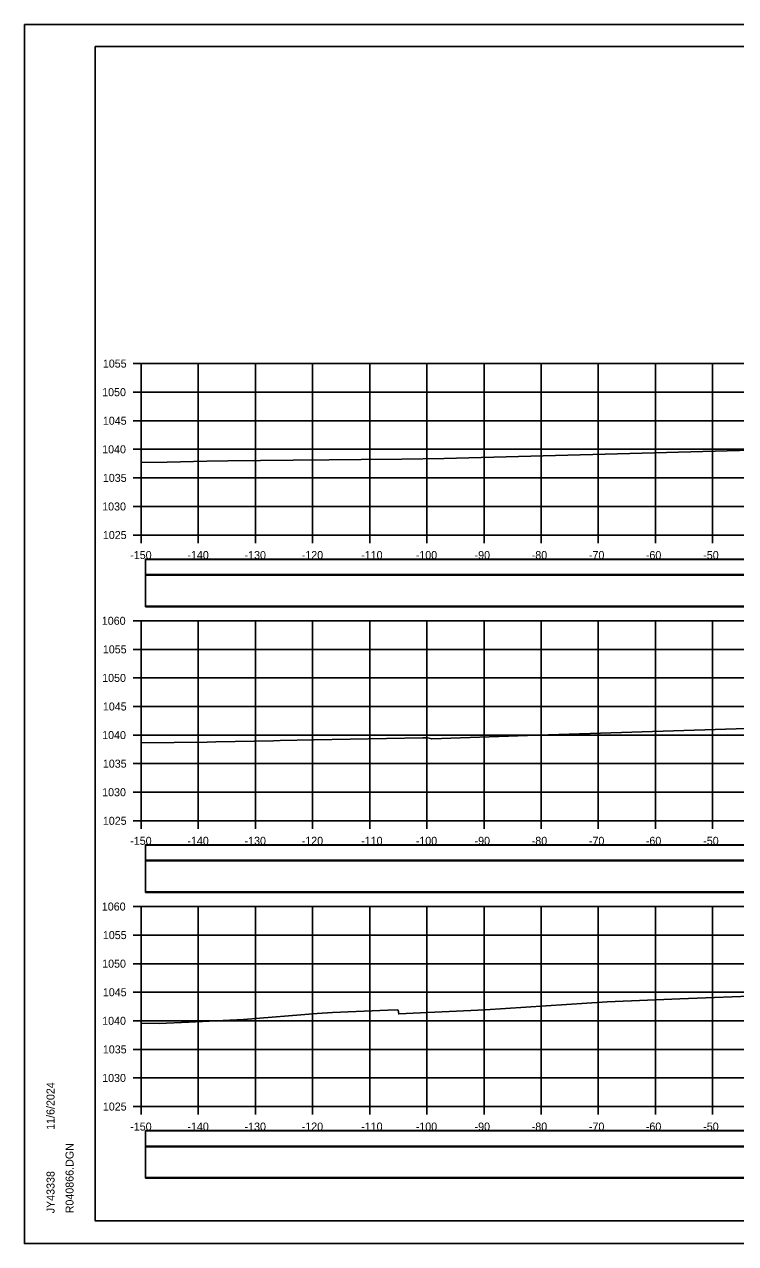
# Model space of a CAD drawing. Extents: x 1370565 to 1374448, y 301010 to 304637.
# Drawn here: x 1373198.4 to 1373322.8, y 301298.3 to 301511.7 of the extents above; entities that cross this region are included whole.
import ezdxf

# ---------------------------------------------------------------- set-up
doc = ezdxf.new("R2010")
doc.units = 0
for name, color, linetype in [('Default', 7, 'Continuous'), ('R_Axis', 7, 'Continuous'), ('R_Axis Annot', 7, 'Continuous'), ('R_Border', 7, 'Continuous'), ('R_Drive', 7, 'Continuous'), ('R_Exist Surface', 7, 'Continuous'), ('R_Grid', 7, 'Continuous'), ('R_No Plot', 7, 'Continuous')]:
    doc.layers.add(name, color=color, linetype=linetype)

msp = doc.modelspace()

# ---------------------------------------------------------------- linework, layer by layer
at = {"layer": 'Default'}
for points in [[(1373219.61, 301415.34), (1373518.02, 301415.34), (1373518.02, 301418.04), (1373219.61, 301418.04)], [(1373219.61, 301409.76), (1373518.02, 301409.76), (1373518.02, 301415.28), (1373219.61, 301415.28)], [(1373219.61, 301365.34), (1373518.02, 301365.34), (1373518.02, 301368.04), (1373219.61, 301368.04)], [(1373219.61, 301359.76), (1373518.02, 301359.76), (1373518.02, 301365.28), (1373219.61, 301365.28)], [(1373219.61, 301315.34), (1373518.02, 301315.34), (1373518.02, 301318.04), (1373219.61, 301318.04)], [(1373219.61, 301309.76), (1373518.02, 301309.76), (1373518.02, 301315.28), (1373219.61, 301315.28)]]:
    msp.add_lwpolyline(points, close=True, dxfattribs=at)
at = {"layer": 'R_Axis'}
for p, q in [((1373217.41, 301452.3), (1373218.81, 301452.3)), ((1373218.81, 301422.3), (1373218.81, 301452.3)), ((1373217.41, 301447.3), (1373218.81, 301447.3)), ((1373217.41, 301442.3), (1373218.81, 301442.3)), ((1373217.41, 301437.3), (1373218.81, 301437.3)), ((1373217.41, 301432.3), (1373218.81, 301432.3)), ((1373217.41, 301427.3), (1373218.81, 301427.3)), ((1373217.41, 301422.3), (1373218.81, 301422.3)), ((1373218.81, 301422.3), (1373518.81, 301422.3)), ((1373218.81, 301420.9), (1373218.81, 301422.3)), ((1373228.81, 301420.9), (1373228.81, 301422.3)), ((1373238.81, 301420.9), (1373238.81, 301422.3)), ((1373248.81, 301420.9), (1373248.81, 301422.3)), ((1373258.81, 301420.9), (1373258.81, 301422.3)), ((1373268.81, 301420.9), (1373268.81, 301422.3)), ((1373278.81, 301420.9), (1373278.81, 301422.3)), ((1373288.81, 301420.9), (1373288.81, 301422.3)), ((1373298.81, 301420.9), (1373298.81, 301422.3)), ((1373308.81, 301420.9), (1373308.81, 301422.3)), ((1373318.81, 301420.9), (1373318.81, 301422.3)), ((1373217.41, 301407.3), (1373218.81, 301407.3)), ((1373218.81, 301372.3), (1373218.81, 301407.3)), ((1373217.41, 301402.3), (1373218.81, 301402.3)), ((1373217.41, 301397.3), (1373218.81, 301397.3)), ((1373217.41, 301392.3), (1373218.81, 301392.3)), ((1373217.41, 301387.3), (1373218.81, 301387.3)), ((1373217.41, 301382.3), (1373218.81, 301382.3)), ((1373217.41, 301377.3), (1373218.81, 301377.3)), ((1373217.41, 301372.3), (1373218.81, 301372.3)), ((1373218.81, 301372.3), (1373518.81, 301372.3)), ((1373218.81, 301370.9), (1373218.81, 301372.3)), ((1373228.81, 301370.9), (1373228.81, 301372.3)), ((1373238.81, 301370.9), (1373238.81, 301372.3)), ((1373248.81, 301370.9), (1373248.81, 301372.3)), ((1373258.81, 301370.9), (1373258.81, 301372.3)), ((1373268.81, 301370.9), (1373268.81, 301372.3)), ((1373278.81, 301370.9), (1373278.81, 301372.3)), ((1373288.81, 301370.9), (1373288.81, 301372.3)), ((1373298.81, 301370.9), (1373298.81, 301372.3)), ((1373308.81, 301370.9), (1373308.81, 301372.3)), ((1373318.81, 301370.9), (1373318.81, 301372.3)), ((1373217.41, 301357.3), (1373218.81, 301357.3)), ((1373218.81, 301322.3), (1373218.81, 301357.3)), ((1373217.41, 301352.3), (1373218.81, 301352.3)), ((1373217.41, 301347.3), (1373218.81, 301347.3)), ((1373217.41, 301342.3), (1373218.81, 301342.3)), ((1373217.41, 301337.3), (1373218.81, 301337.3)), ((1373217.41, 301332.3), (1373218.81, 301332.3)), ((1373217.41, 301327.3), (1373218.81, 301327.3)), ((1373217.41, 301322.3), (1373218.81, 301322.3)), ((1373218.81, 301322.3), (1373518.81, 301322.3)), ((1373218.81, 301320.9), (1373218.81, 301322.3)), ((1373228.81, 301320.9), (1373228.81, 301322.3)), ((1373238.81, 301320.9), (1373238.81, 301322.3)), ((1373248.81, 301320.9), (1373248.81, 301322.3)), ((1373258.81, 301320.9), (1373258.81, 301322.3)), ((1373268.81, 301320.9), (1373268.81, 301322.3)), ((1373278.81, 301320.9), (1373278.81, 301322.3)), ((1373288.81, 301320.9), (1373288.81, 301322.3)), ((1373298.81, 301320.9), (1373298.81, 301322.3)), ((1373308.81, 301320.9), (1373308.81, 301322.3)), ((1373318.81, 301320.9), (1373318.81, 301322.3))]:
    msp.add_line(p, q, dxfattribs=at)
at = {"layer": 'R_Border'}
for p, q in [((1373210.81, 301507.76), (1373526.99, 301507.76)), ((1373210.81, 301302.3), (1373210.81, 301507.76)), ((1373210.81, 301302.3), (1373210.81, 301302.3)), ((1373526.99, 301302.3), (1373210.81, 301302.3))]:
    msp.add_line(p, q, dxfattribs=at)
at = {"layer": 'R_Drive'}
for points in [[(1373219.61, 301415.39), (1373518.02, 301415.39), (1373518.02, 301418.1), (1373219.61, 301418.1)], [(1373219.61, 301409.87), (1373518.02, 301409.87), (1373518.02, 301415.39), (1373219.61, 301415.39)], [(1373219.61, 301365.39), (1373518.02, 301365.39), (1373518.02, 301368.1), (1373219.61, 301368.1)], [(1373219.61, 301359.87), (1373518.02, 301359.87), (1373518.02, 301365.39), (1373219.61, 301365.39)], [(1373219.61, 301315.39), (1373518.02, 301315.39), (1373518.02, 301318.1), (1373219.61, 301318.1)], [(1373219.61, 301309.87), (1373518.02, 301309.87), (1373518.02, 301315.39), (1373219.61, 301315.39)]]:
    msp.add_lwpolyline(points, close=True, dxfattribs=at)
at = {"layer": 'R_Exist Surface'}
for points in [[(1373218.81, 301434.97), (1373223.38, 301435.07), (1373230.3, 301435.24), (1373233.98, 301435.28), (1373245.42, 301435.42), (1373251.72, 301435.47), (1373257.32, 301435.53), (1373264.46, 301435.6), (1373271.87, 301435.68), (1373304.34, 301436.57), (1373342.67, 301437.61)], [(1373218.81, 301385.97), (1373230.41, 301386.07), (1373231.88, 301386.09), (1373241.97, 301386.31), (1373243.14, 301386.33), (1373249.06, 301386.44), (1373268.11, 301386.81), (1373268.93, 301386.81), (1373269.21, 301386.75), (1373269.66, 301386.64), (1373286.43, 301387.2), (1373331.99, 301388.66)], [(1373218.81, 301336.87), (1373221.97, 301336.86), (1373227.19, 301337.06), (1373236.75, 301337.55), (1373249.61, 301338.61), (1373252.31, 301338.73), (1373261.98, 301339.17), (1373263.75, 301339.22), (1373263.77, 301339.17), (1373263.91, 301338.51), (1373279.03, 301339.2), (1373300.38, 301340.62), (1373313.09, 301341.13), (1373328.29, 301341.75)]]:
    msp.add_lwpolyline(points, dxfattribs=at)
at = {"layer": 'R_Grid'}
for p, q in [((1373218.81, 301452.3), (1373518.81, 301452.3)), ((1373218.81, 301422.3), (1373218.81, 301452.3)), ((1373228.81, 301422.3), (1373228.81, 301452.3)), ((1373238.81, 301422.3), (1373238.81, 301452.3)), ((1373248.81, 301422.3), (1373248.81, 301452.3)), ((1373258.81, 301422.3), (1373258.81, 301452.3)), ((1373268.81, 301422.3), (1373268.81, 301452.3)), ((1373278.81, 301422.3), (1373278.81, 301452.3)), ((1373288.81, 301422.3), (1373288.81, 301452.3)), ((1373298.81, 301422.3), (1373298.81, 301452.3)), ((1373308.81, 301422.3), (1373308.81, 301452.3)), ((1373318.81, 301422.3), (1373318.81, 301452.3)), ((1373218.81, 301447.3), (1373518.81, 301447.3)), ((1373218.81, 301442.3), (1373518.81, 301442.3)), ((1373218.81, 301437.3), (1373518.81, 301437.3)), ((1373218.81, 301432.3), (1373518.81, 301432.3)), ((1373218.81, 301427.3), (1373518.81, 301427.3)), ((1373218.81, 301422.3), (1373518.81, 301422.3)), ((1373218.81, 301407.3), (1373518.81, 301407.3)), ((1373218.81, 301372.3), (1373218.81, 301407.3)), ((1373228.81, 301372.3), (1373228.81, 301407.3)), ((1373238.81, 301372.3), (1373238.81, 301407.3)), ((1373248.81, 301372.3), (1373248.81, 301407.3)), ((1373258.81, 301372.3), (1373258.81, 301407.3)), ((1373268.81, 301372.3), (1373268.81, 301407.3)), ((1373278.81, 301372.3), (1373278.81, 301407.3)), ((1373288.81, 301372.3), (1373288.81, 301407.3)), ((1373298.81, 301372.3), (1373298.81, 301407.3)), ((1373308.81, 301372.3), (1373308.81, 301407.3)), ((1373318.81, 301372.3), (1373318.81, 301407.3)), ((1373218.81, 301402.3), (1373518.81, 301402.3)), ((1373218.81, 301397.3), (1373518.81, 301397.3)), ((1373218.81, 301392.3), (1373518.81, 301392.3)), ((1373218.81, 301387.3), (1373518.81, 301387.3)), ((1373218.81, 301382.3), (1373518.81, 301382.3)), ((1373218.81, 301377.3), (1373518.81, 301377.3)), ((1373218.81, 301372.3), (1373518.81, 301372.3)), ((1373218.81, 301357.3), (1373518.81, 301357.3)), ((1373218.81, 301322.3), (1373218.81, 301357.3)), ((1373228.81, 301322.3), (1373228.81, 301357.3)), ((1373238.81, 301322.3), (1373238.81, 301357.3)), ((1373248.81, 301322.3), (1373248.81, 301357.3)), ((1373258.81, 301322.3), (1373258.81, 301357.3)), ((1373268.81, 301322.3), (1373268.81, 301357.3)), ((1373278.81, 301322.3), (1373278.81, 301357.3)), ((1373288.81, 301322.3), (1373288.81, 301357.3)), ((1373298.81, 301322.3), (1373298.81, 301357.3)), ((1373308.81, 301322.3), (1373308.81, 301357.3)), ((1373318.81, 301322.3), (1373318.81, 301357.3)), ((1373218.81, 301352.3), (1373518.81, 301352.3)), ((1373218.81, 301347.3), (1373518.81, 301347.3)), ((1373218.81, 301342.3), (1373518.81, 301342.3)), ((1373218.81, 301337.3), (1373518.81, 301337.3)), ((1373218.81, 301332.3), (1373518.81, 301332.3)), ((1373218.81, 301327.3), (1373518.81, 301327.3)), ((1373218.81, 301322.3), (1373518.81, 301322.3))]:
    msp.add_line(p, q, dxfattribs=at)
at = {"layer": 'R_No Plot'}
for p, q in [((1373198.41, 301511.65), (1373531.75, 301511.65)), ((1373198.41, 301298.32), (1373531.75, 301298.32))]:
    msp.add_line(p, q, dxfattribs=at)
for points in [[(1373198.41, 301511.65), (1373531.75, 301511.65), (1373531.75, 301298.32), (1373198.41, 301298.32)], [(1373444.73, 301507.76), (1373464.35, 301507.76), (1373464.35, 301497.88), (1373480.47, 301497.88), (1373503.67, 301497.88), (1373503.67, 301473.55), (1373526.99, 301473.55), (1373526.99, 301302.3), (1373210.81, 301302.3), (1373210.81, 301507.76)]]:
    msp.add_lwpolyline(points, close=True, dxfattribs=at)

# ---------------------------------------------------------------- texts
at = {"layer": 'R_Axis Annot'}
for s, p in [('1055', (1373212.13, 301451.6)), ('1050', (1373212.01, 301446.6)), ('1045', (1373212.13, 301441.6)), ('1040', (1373212.01, 301436.6)), ('1035', (1373212.13, 301431.6)), ('1030', (1373212.01, 301426.6)), ('1025', (1373212.13, 301421.6)), ('-150', (1373216.92, 301418.1)), ('-140', (1373226.92, 301418.1)), ('-130', (1373236.92, 301418.1)), ('-120', (1373246.92, 301418.1)), ('-110', (1373257.32, 301418.1)), ('-100', (1373266.87, 301418.1)), ('-90', (1373277.16, 301418.1)), ('-80', (1373287.16, 301418.1)), ('-70', (1373297.16, 301418.1)), ('-60', (1373307.12, 301418.1)), ('-50', (1373317.16, 301418.1)), ('1060', (1373211.95, 301406.6)), ('1055', (1373212.13, 301401.6)), ('1050', (1373212.01, 301396.6)), ('1045', (1373212.13, 301391.6)), ('1040', (1373212.01, 301386.6)), ('1035', (1373212.13, 301381.6)), ('1030', (1373212.01, 301376.6)), ('1025', (1373212.13, 301371.6)), ('-150', (1373216.92, 301368.1)), ('-140', (1373226.92, 301368.1)), ('-130', (1373236.92, 301368.1)), ('-120', (1373246.92, 301368.1)), ('-110', (1373257.32, 301368.1)), ('-100', (1373266.87, 301368.1)), ('-90', (1373277.16, 301368.1)), ('-80', (1373287.16, 301368.1)), ('-70', (1373297.16, 301368.1)), ('-60', (1373307.12, 301368.1)), ('-50', (1373317.16, 301368.1)), ('1060', (1373211.95, 301356.6)), ('1055', (1373212.13, 301351.6)), ('1050', (1373212.01, 301346.6)), ('1045', (1373212.13, 301341.6)), ('1040', (1373212.01, 301336.6)), ('1035', (1373212.13, 301331.6)), ('1030', (1373212.01, 301326.6)), ('1025', (1373212.13, 301321.6)), ('-150', (1373216.92, 301318.1)), ('-140', (1373226.92, 301318.1)), ('-130', (1373236.92, 301318.1)), ('-120', (1373246.92, 301318.1)), ('-110', (1373257.32, 301318.1)), ('-100', (1373266.87, 301318.1)), ('-90', (1373277.16, 301318.1)), ('-80', (1373287.16, 301318.1)), ('-70', (1373297.16, 301318.1)), ('-60', (1373307.12, 301318.1)), ('-50', (1373317.16, 301318.1))]:
    msp.add_text(s, height=1.4, dxfattribs=at).set_placement(p)
at = {"layer": 'R_Border'}
for s, p in [('11/6/2024', (1373203.68, 301318.23)), ('R040866.DGN', (1373207.01, 301303.62)), ('JY43338', (1373203.68, 301303.62))]:
    msp.add_text(s, height=1.4, rotation=90, dxfattribs=at).set_placement(p)

doc.saveas('drawing.dxf')
